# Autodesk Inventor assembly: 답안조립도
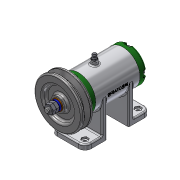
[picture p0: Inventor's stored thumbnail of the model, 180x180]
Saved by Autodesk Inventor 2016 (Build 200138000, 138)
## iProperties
Created: 2017-02
Part Number: 답안조립도
Material: 일반
Document SubType Name: Assembly
Designer: H
Author: H
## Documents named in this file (16)
- C:\Users\CAMTIC\Desktop\470207V1010\답안조립도.iam
- C:\Users\CAMTIC\Desktop\470207V1010\본체.ipt
- C:\Users\CAMTIC\Desktop\470207V1010\V벨트풀리.ipt
- C:\Users\CAMTIC\Desktop\470207V1010\너트 M 8.ipt
- C:\Users\CAMTIC\Desktop\470207V1010\니플 M 6 x 0.75.ipt
- C:\Users\CAMTIC\Desktop\470207V1010\뒤커버.ipt
- C:\Users\CAMTIC\Desktop\470207V1010\베어링 15 x 32 x 9.ipt
- C:\Users\CAMTIC\Desktop\470207V1010\볼트 M 6 x 8.ipt
- C:\Users\CAMTIC\Desktop\470207V1010\볼트 M4 x 12.ipt
- C:\Users\CAMTIC\Desktop\470207V1010\스프링와셔 8.ipt
- C:\Users\CAMTIC\Desktop\470207V1010\앞커버.ipt
- C:\Users\CAMTIC\Desktop\470207V1010\오일 실 15 25 7.ipt
- C:\Users\CAMTIC\Desktop\470207V1010\와셔 6x11.5.ipt
- C:\Users\CAMTIC\Desktop\470207V1010\와셔 8x17.ipt
- C:\Users\CAMTIC\Desktop\470207V1010\축.ipt
- C:\Users\CAMTIC\Desktop\470207V1010\키 3 x 3 x 12.ipt
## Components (11 placed, 3 different names)
1. V벨트풀리:1
2. KS B 2023 6002 - 15 x 32 x 9:1
3. KS B 2023 6002 - 15 x 32 x 9:2
4. ISO 4762 M4 x 12:2
5. ISO 4762 M4 x 12:3
6. ISO 4762 M4 x 12:4
7. ISO 4762 M4 x 12:5
8. ISO 4762 M4 x 12:1
9. ISO 4762 M4 x 12:6
10. ISO 4762 M4 x 12:7
11. ISO 4762 M4 x 12:8
